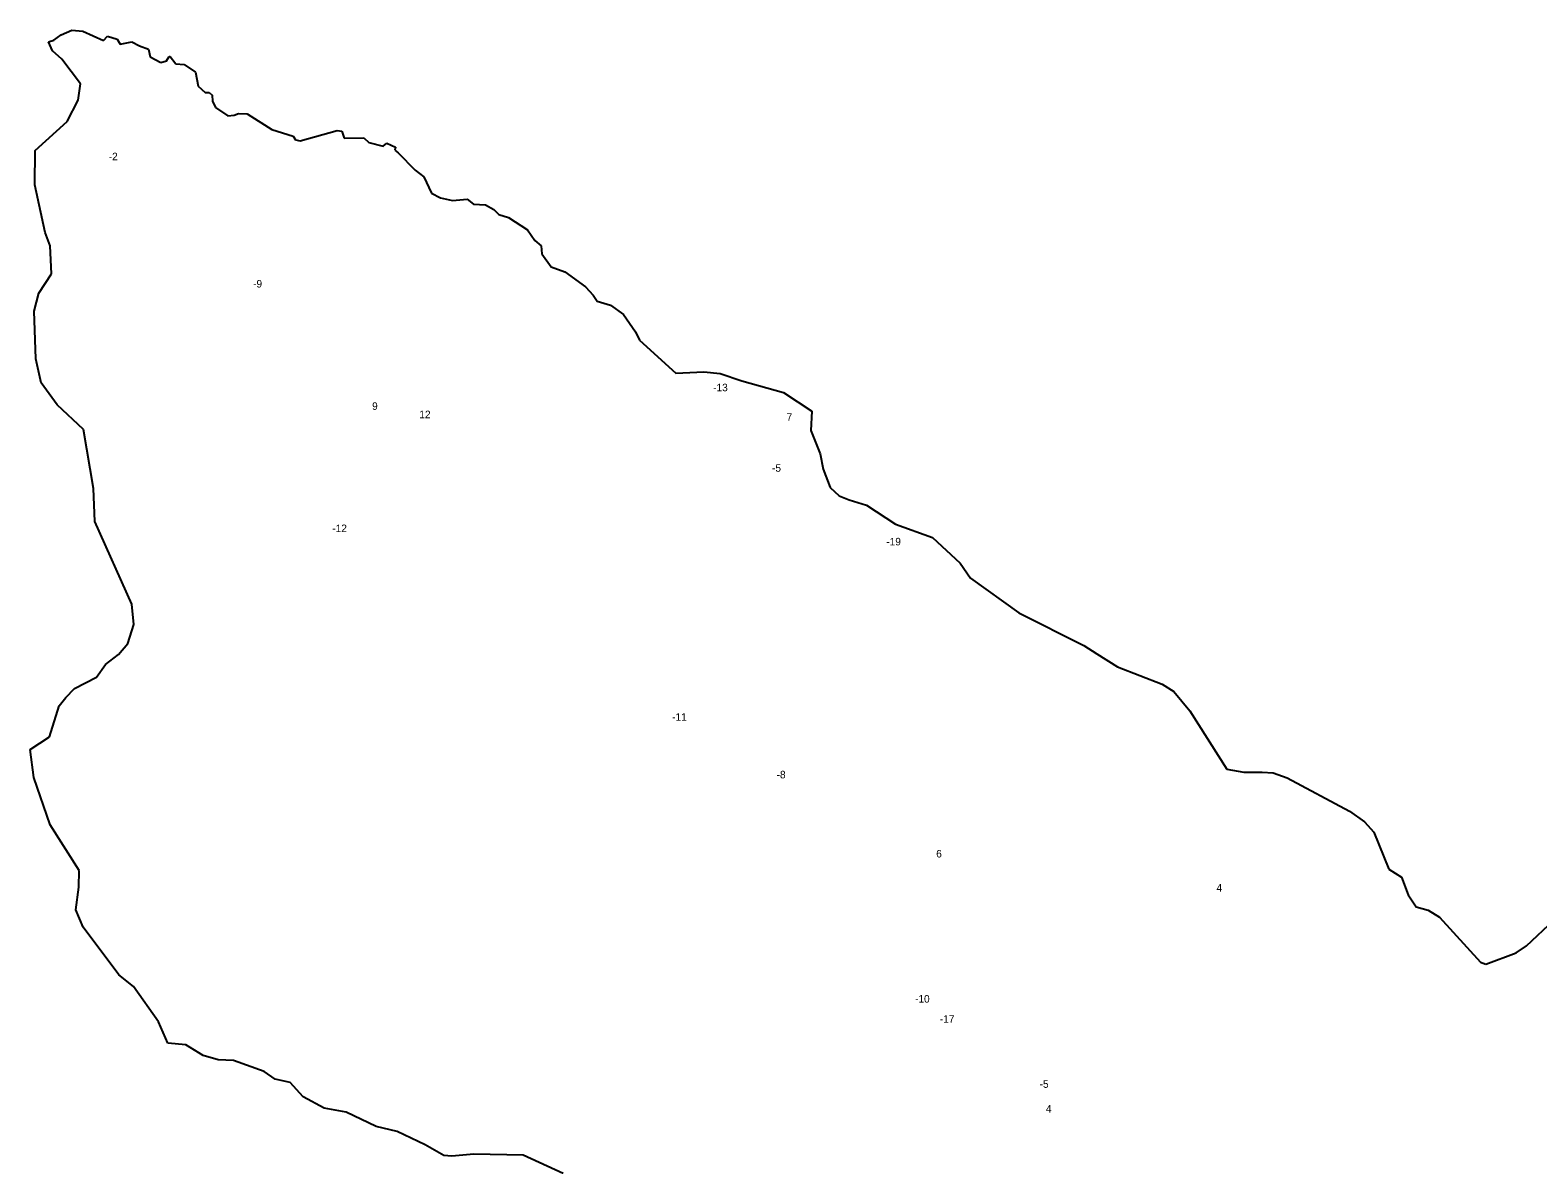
# Model space of a CAD drawing. Extents: x -791694 to -787831, y -969302 to -965696.
# Drawn here: x -791694 to -789697, y -967213 to -965709 of the extents above; entities that cross this region are included whole.
import ezdxf

# ---------------------------------------------------------------- set-up
doc = ezdxf.new("R2010")
doc.units = 0
doc.layers.add('Vrstva 13', color=7, linetype='Continuous')
doc.layers.add('Vrstva 15', color=7, linetype='Continuous')

msp = doc.modelspace()

# ---------------------------------------------------------------- linework, layer by layer
at = {"layer": 'Vrstva 13'}
for p, q in [((-791653.57, -965715.24), (-791639.24, -965709.24)), ((-791639.24, -965709.24), (-791624.57, -965710.41)), ((-791624.57, -965710.41), (-791597.07, -965722.75)), ((-791670.33, -965724.83), (-791663.07, -965722.58)), ((-791664.66, -965736.83), (-791670.33, -965724.83)), ((-791663.07, -965722.58), (-791653.57, -965715.24)), ((-791597.07, -965722.75), (-791592.07, -965717.08)), ((-791592.07, -965717.08), (-791579.07, -965721.41)), ((-791579.07, -965721.41), (-791575.07, -965727.92)), ((-791575.07, -965727.92), (-791559.57, -965724.92)), ((-791559.57, -965724.92), (-791549.73, -965730.08)), ((-791549.73, -965730.08), (-791537.57, -965734.25)), ((-791652.66, -965747.51), (-791664.66, -965736.83)), ((-791627.66, -965780.52), (-791652.66, -965747.51)), ((-791537.57, -965734.25), (-791535.23, -965744.42)), ((-791535.23, -965744.42), (-791521.23, -965752.09)), ((-791521.23, -965752.09), (-791513.89, -965750.09)), ((-791513.89, -965750.09), (-791510.39, -965744.26)), ((-791510.39, -965744.26), (-791508.73, -965744.26)), ((-791508.73, -965744.26), (-791501.39, -965753.93)), ((-791501.39, -965753.93), (-791490.39, -965754.59)), ((-791490.39, -965754.59), (-791475.39, -965764.93)), ((-791475.39, -965764.93), (-791472.06, -965783.44)), ((-791630.66, -965802.2), (-791627.66, -965780.52)), ((-791472.06, -965783.44), (-791462.39, -965791.78)), ((-791462.39, -965791.78), (-791457.06, -965791.94)), ((-791457.06, -965791.94), (-791453.39, -965795.44)), ((-791645.33, -965830.21), (-791630.66, -965802.2)), ((-791453.39, -965795.44), (-791452.89, -965803.44)), ((-791452.89, -965803.44), (-791449.06, -965811.94)), ((-791449.06, -965811.94), (-791432.39, -965822.62)), ((-791687.66, -965868.89), (-791645.33, -965830.21)), ((-791432.39, -965822.62), (-791424.05, -965821.95)), ((-791424.05, -965821.95), (-791418.39, -965819.78)), ((-791418.39, -965819.78), (-791406.89, -965820.11)), ((-791406.89, -965820.11), (-791374.22, -965841.13)), ((-791374.22, -965841.13), (-791346.05, -965849.96)), ((-791346.05, -965849.96), (-791342.89, -965854.8)), ((-791336.89, -965856.13), (-791287.55, -965842.29)), ((-791287.55, -965842.29), (-791281.55, -965843.3)), ((-791281.55, -965843.3), (-791278.38, -965852.3)), ((-791278.38, -965852.3), (-791252.37, -965852.13)), ((-791252.37, -965852.13), (-791245.87, -965858.3)), ((-791688.33, -965914.24), (-791687.66, -965868.89)), ((-791342.89, -965854.8), (-791336.89, -965856.13)), ((-791245.87, -965858.3), (-791226.7, -965863.14)), ((-791226.7, -965863.14), (-791221.87, -965858.97)), ((-791221.87, -965858.97), (-791210.37, -965864.47)), ((-791210.37, -965864.47), (-791211.37, -965868.47)), ((-791211.37, -965868.47), (-791206.7, -965871.64)), ((-791206.7, -965871.64), (-791184.53, -965894.98)), ((-791184.53, -965894.98), (-791173.03, -965903.65)), ((-791173.03, -965903.65), (-791162.7, -965925.33)), ((-791674.77, -965977.62), (-791688.33, -965914.24)), ((-791162.7, -965925.33), (-791150.69, -965931.34)), ((-791150.69, -965931.34), (-791135.03, -965934.84)), ((-791135.03, -965934.84), (-791115.36, -965933.17)), ((-791115.36, -965933.17), (-791107.03, -965939.67)), ((-791107.03, -965939.67), (-791091.19, -965940.84)), ((-791091.19, -965940.84), (-791080.19, -965947.01)), ((-791080.19, -965947.01), (-791073.52, -965953.51)), ((-791073.52, -965953.51), (-791060.86, -965957.35)), ((-791060.86, -965957.35), (-791035.69, -965973.85)), ((-791668.1, -965994.97), (-791674.77, -965977.62)), ((-791035.69, -965973.85), (-791025.85, -965987.86)), ((-791025.85, -965987.86), (-791017.51, -965995.2)), ((-791666.1, -966032.32), (-791668.1, -965994.97)), ((-791017.51, -965995.2), (-791016.35, -966005.7)), ((-791016.35, -966005.7), (-791004.18, -966022.88)), ((-791004.18, -966022.88), (-790986.18, -966029.38)), ((-790986.18, -966029.38), (-790958.84, -966049.55)), ((-791683.1, -966057.66), (-791666.1, -966032.32)), ((-790958.84, -966049.55), (-790948.68, -966060.56)), ((-791689.11, -966081.67), (-791683.1, -966057.66)), ((-790948.68, -966060.56), (-790943.08, -966068.32)), ((-790943.08, -966068.32), (-790925.75, -966073.65)), ((-791687.11, -966144.7), (-791689.11, -966081.67)), ((-790925.75, -966073.65), (-790908.41, -966086.33)), ((-790908.41, -966086.33), (-790892.41, -966109)), ((-790892.41, -966109), (-790887.08, -966120.34)), ((-790887.08, -966120.34), (-790839.08, -966163.69)), ((-791679.77, -966176.72), (-791687.11, -966144.7)), ((-790839.08, -966163.69), (-790801.74, -966162.03)), ((-790801.74, -966162.03), (-790780.07, -966164.36)), ((-790780.07, -966164.36), (-790751.41, -966174.03)), ((-791658.44, -966205.73), (-791679.77, -966176.72)), ((-790751.41, -966174.03), (-790696.4, -966189.7)), ((-790696.4, -966189.7), (-790658.74, -966214.38)), ((-791623.77, -966238.74), (-791658.44, -966205.73)), ((-790658.74, -966214.38), (-790660.07, -966240.06)), ((-791610.44, -966316.78), (-791623.77, -966238.74)), ((-790660.07, -966240.06), (-790647.74, -966270.74)), ((-790647.74, -966270.74), (-790643.74, -966291.08)), ((-790643.74, -966291.08), (-790634.41, -966315.43)), ((-791608.77, -966360.47), (-791610.44, -966316.78)), ((-790634.41, -966315.43), (-790622.4, -966326.43)), ((-790622.4, -966326.43), (-790609.4, -966331.77)), ((-790609.4, -966331.77), (-790586.4, -966338.77)), ((-790586.4, -966338.77), (-790548.07, -966364.11)), ((-791559.78, -966470.19), (-791608.77, -966360.47)), ((-790548.07, -966364.11), (-790498.73, -966381.46)), ((-790498.73, -966381.46), (-790462.4, -966415.81)), ((-790462.4, -966415.81), (-790448.73, -966435.48)), ((-790448.73, -966435.48), (-790384.39, -966481.5)), ((-791557.11, -966496.87), (-791559.78, -966470.19)), ((-790384.39, -966481.5), (-790298.39, -966524.85)), ((-791565.11, -966522.21), (-791557.11, -966496.87)), ((-791577.45, -966536.88), (-791565.11, -966522.21)), ((-790298.39, -966524.85), (-790281.06, -966535.86)), ((-791606.44, -966566.9), (-791594.77, -966549.89)), ((-791594.77, -966549.89), (-791577.45, -966536.88)), ((-790281.06, -966535.86), (-790253.72, -966553.2)), ((-791635.78, -966581.9), (-791606.44, -966566.9)), ((-790253.72, -966553.2), (-790194.73, -966575.87)), ((-791647.11, -966593.58), (-791635.78, -966581.9)), ((-790194.73, -966575.87), (-790179.06, -966585.87)), ((-790179.06, -966585.87), (-790158.06, -966611.22)), ((-791668.78, -966645.93), (-791656.11, -966604.58)), ((-791656.11, -966604.58), (-791647.11, -966593.58)), ((-790158.06, -966611.22), (-790108.72, -966688.92)), ((-791694.45, -966662.61), (-791668.78, -966645.93)), ((-791689.78, -966699.95), (-791694.45, -966662.61)), ((-790108.72, -966688.92), (-790086.39, -966692.92)), ((-791667.78, -966762.65), (-791689.78, -966699.95)), ((-790086.39, -966692.92), (-790062.06, -966692.58)), ((-790062.06, -966692.58), (-790047.39, -966693.58)), ((-790047.39, -966693.58), (-790029.06, -966700.25)), ((-790029.06, -966700.25), (-789946.39, -966744.27)), ((-789946.39, -966744.27), (-789926.72, -966758.61)), ((-791629.44, -966823.01), (-791667.78, -966762.65)), ((-789926.72, -966758.61), (-789914.38, -966772.28)), ((-789914.38, -966772.28), (-789894.38, -966821.31)), ((-791629.78, -966845.02), (-791629.44, -966823.01)), ((-789894.38, -966821.31), (-789877.38, -966831.65)), ((-791634.12, -966875.36), (-791629.78, -966845.02)), ((-789877.38, -966831.65), (-789868.71, -966855.32)), ((-789868.71, -966855.32), (-789858.05, -966871)), ((-789858.05, -966871), (-789842.38, -966875.67)), ((-791624.12, -966898.04), (-791634.12, -966875.36)), ((-789842.38, -966875.67), (-789827.04, -966885)), ((-789827.04, -966885), (-789773.04, -966944.36)), ((-789711.7, -966922.67), (-789675.03, -966888.32)), ((-791577.11, -966961.4), (-791624.12, -966898.04)), ((-789725.7, -966932.01), (-789711.7, -966922.67)), ((-789773.04, -966944.36), (-789765.71, -966947.03)), ((-789765.71, -966947.03), (-789725.7, -966932.01)), ((-791557.45, -966976.74), (-791577.11, -966961.4)), ((-791524.45, -967023.76), (-791557.45, -966976.74)), ((-791512.11, -967052.1), (-791524.45, -967023.76)), ((-791488.11, -967054.1), (-791512.11, -967052.1)), ((-791465.11, -967068.11), (-791488.11, -967054.1)), ((-791445.44, -967073.78), (-791465.11, -967068.11)), ((-791425.1, -967074.78), (-791445.44, -967073.78)), ((-791384.43, -967089.45), (-791425.1, -967074.78)), ((-791369.77, -967099.79), (-791384.43, -967089.45)), ((-791349.76, -967104.12), (-791369.77, -967099.79)), ((-791332.76, -967122.8), (-791349.76, -967104.12)), ((-791305.1, -967138.14), (-791332.76, -967122.8)), ((-791275.76, -967143.47), (-791305.1, -967138.14)), ((-791236.09, -967162.48), (-791275.76, -967143.47)), ((-791208.1, -967169.15), (-791236.09, -967162.48)), ((-791171.1, -967186.49), (-791208.1, -967169.15)), ((-791146.43, -967200.83), (-791171.1, -967186.49)), ((-791135.76, -967201.83), (-791146.43, -967200.83)), ((-791106.76, -967198.83), (-791135.76, -967201.83)), ((-791041.43, -967200.16), (-791106.76, -967198.83)), ((-790988.42, -967224.5), (-791041.43, -967200.16))]:
    msp.add_line(p, q, dxfattribs=at)

# ---------------------------------------------------------------- texts
at = {"layer": 'Vrstva 15'}
for s, p in [('-2', (-791590.34, -965881.74)), ('-9', (-791399.044, -966050.39)), ('-13', (-790789.514, -966187.87)), ('9', (-791241.38, -966212.55)), ('12', (-791178.781, -966223.55)), ('7', (-790692.216, -966226.97)), ('-5', (-790711.5, -966294.52)), ('-12', (-791294.114, -966374.53)), ('-19', (-790560.068, -966392.14)), ('-11', (-790843.919, -966624.64)), ('-8', (-790705.44, -966700.94)), ('6', (-790494, -966805.8)), ('4', (-790122.632, -966850.99)), ('-10', (-790522.015, -966998.14)), ('-17', (-790489.184, -967024.88)), ('-5', (-790356.97, -967111.04)), ('4', (-790348.632, -967143.78))]:
    msp.add_text(s, height=10, dxfattribs=at).set_placement(p)

doc.saveas('drawing.dxf')
